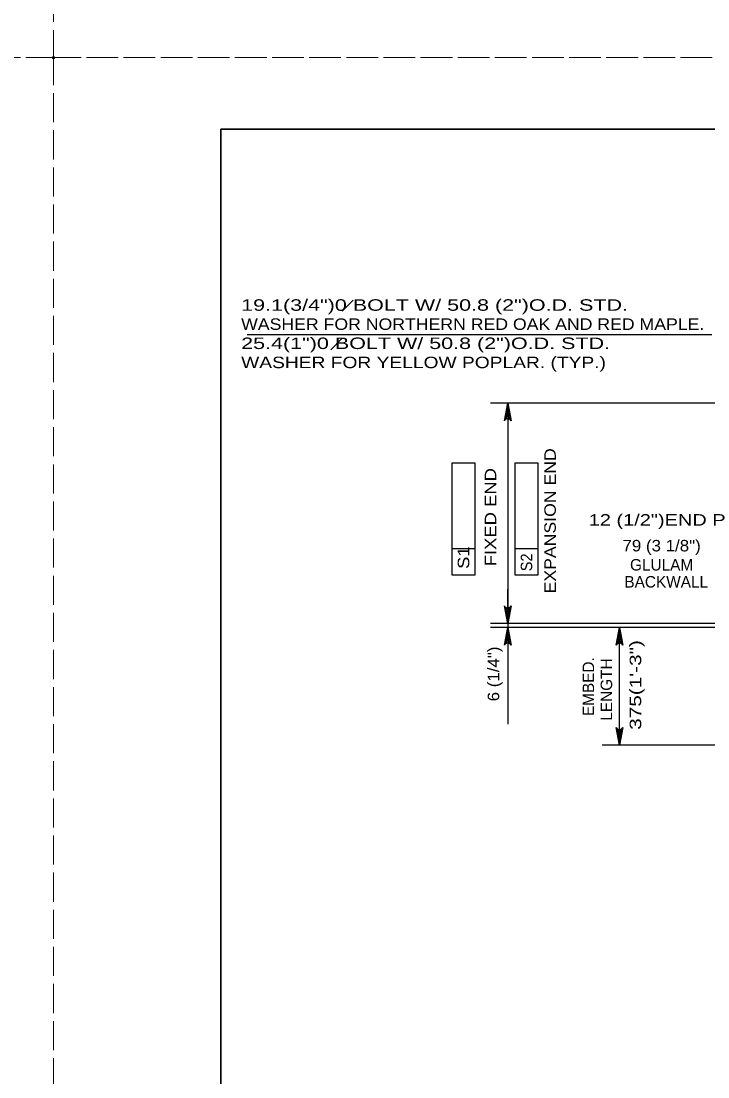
# Model space of a CAD drawing. Extents: x -11 to 79, y -154 to 0.
# Drawn here: x 33.66 to 40.84, y -32.65 to -21.62 of the extents above; entities that cross this region are included whole.
import ezdxf
from ezdxf.enums import TextEntityAlignment as Align

# ---------------------------------------------------------------- set-up
doc = ezdxf.new("R2010")
doc.units = 0
doc.header["$LTSCALE"] = 0.048
doc.header["$PDMODE"] = 32
doc.header["$PDSIZE"] = 0.024
doc.linetypes.add('LONG_DASHED', pattern=[7.5, 6, -1.5])
for name, color, linetype, lineweight in [('1', 7, 'Continuous', 25), ('3', 7, 'Continuous', 25), ('63', 7, 'LONG_DASHED', 13)]:
    doc.layers.add(name, color=color, linetype=linetype, lineweight=lineweight)
doc.layers.add('62', color=7, linetype='Continuous')

msp = doc.modelspace()

# ---------------------------------------------------------------- hatches: boundary and pattern name
at = {"layer": '3'}
for points in [[(38.726, -25.73242), (38.766, -25.73242), (38.746, -25.61242)], [(38.726, -27.79692), (38.766, -27.79692), (38.746, -27.91692)], [(38.726, -28.0765), (38.766, -28.0765), (38.746, -27.9565)], [(39.89308, -28.0765), (39.93308, -28.0765), (39.91308, -27.9565)], [(39.89308, -29.06908), (39.93308, -29.06908), (39.91308, -29.18908)]]:
    msp.add_hatch(color=256, dxfattribs=at).paths.add_polyline_path(points)

# ---------------------------------------------------------------- linework, layer by layer
at = {"layer": '1', "lineweight": 35}
msp.add_lwpolyline([(35.75, -43.25), (67.25, -43.25), (67.25, -22.75), (35.75, -22.75)], close=True, dxfattribs=at)
at = {"layer": '3', "lineweight": 35}
for p, q in [((37.13225, -24.53483), (37.01542, -24.65167)), ((37.01425, -24.93692), (36.89742, -25.05375))]:
    msp.add_line(p, q, dxfattribs=at)
at = {"layer": '3'}
for p, q in [((40.87825, -24.89725), (36.02317, -24.89725)), ((41.44975, -25.61242), (38.566, -25.61242)), ((39.63817, -25.61242), (38.566, -25.61242)), ((38.746, -25.61242), (38.746, -27.7765)), ((38.746, -25.73242), (38.746, -27.79692)), ((38.16517, -26.23492), (38.40142, -26.23492)), ((38.40142, -26.23492), (38.40142, -27.41075)), ((38.82317, -27.41075), (38.82317, -26.23492)), ((38.82317, -26.23492), (39.05942, -26.23492)), ((38.40142, -27.13517), (38.16517, -27.13517)), ((39.05942, -27.13517), (38.82317, -27.13517)), ((38.746, -27.73692), (38.746, -27.55692)), ((38.746, -27.79692), (38.746, -27.67692)), ((41.44975, -27.91692), (38.566, -27.91692)), ((39.63817, -27.91692), (38.566, -27.91692)), ((38.746, -27.91692), (38.746, -27.9565)), ((41.79425, -27.9565), (38.566, -27.9565)), ((38.6835, -27.9565), (38.566, -27.9565)), ((41.44975, -27.9565), (39.73308, -27.9565)), ((39.85058, -27.9565), (39.73308, -27.9565)), ((39.91308, -29.18908), (39.91308, -27.9565)), ((38.746, -28.0765), (38.746, -28.1965)), ((38.746, -28.1365), (38.746, -28.96875)), ((39.91308, -29.06908), (39.91308, -28.0765)), ((42.62758, -29.18908), (39.73308, -29.18908)), ((39.85058, -29.18908), (39.73308, -29.18908))]:
    msp.add_line(p, q, dxfattribs=at)
for points in [[(38.746, -25.61242), (38.78092, -25.79883), (38.771, -25.7845), (38.7585, -25.77708), (38.746, -25.77492), (38.7335, -25.77708), (38.721, -25.7845), (38.71108, -25.79883), (38.746, -25.61242), (38.721, -25.7845), (38.7335, -25.77708), (38.746, -25.61242), (38.746, -25.77492), (38.7585, -25.77708), (38.746, -25.61242), (38.771, -25.7845)], [(38.40142, -27.41075), (38.16517, -27.41075), (38.16517, -26.23492)], [(39.05942, -26.23492), (39.05942, -27.41075), (38.82317, -27.41075)], [(38.746, -27.91692), (38.71108, -27.7305), (38.721, -27.74483), (38.7335, -27.75225), (38.746, -27.75442), (38.7585, -27.75225), (38.771, -27.74483), (38.78092, -27.7305), (38.746, -27.91692), (38.771, -27.74483), (38.7585, -27.75225), (38.746, -27.91692), (38.746, -27.75442), (38.7335, -27.75225), (38.746, -27.91692), (38.721, -27.74483)], [(38.746, -27.9565), (38.78092, -28.14292), (38.771, -28.12858), (38.7585, -28.12117), (38.746, -28.119), (38.7335, -28.12117), (38.721, -28.12858), (38.71108, -28.14292), (38.746, -27.9565), (38.721, -28.12858), (38.7335, -28.12117), (38.746, -27.9565), (38.746, -28.119), (38.7585, -28.12117), (38.746, -27.9565), (38.771, -28.12858)], [(39.91308, -27.9565), (39.948, -28.14292), (39.93808, -28.12858), (39.92558, -28.12117), (39.91308, -28.119), (39.90058, -28.12117), (39.88808, -28.12858), (39.87817, -28.14292), (39.91308, -27.9565), (39.88808, -28.12858), (39.90058, -28.12117), (39.91308, -27.9565), (39.91308, -28.119), (39.92558, -28.12117), (39.91308, -27.9565), (39.93808, -28.12858)], [(39.91308, -29.18908), (39.87817, -29.00267), (39.88808, -29.017), (39.90058, -29.02442), (39.91308, -29.02658), (39.92558, -29.02442), (39.93808, -29.017), (39.948, -29.00267), (39.91308, -29.18908), (39.93808, -29.017), (39.92558, -29.02442), (39.91308, -29.18908), (39.91308, -29.02658), (39.90058, -29.02442), (39.91308, -29.18908), (39.88808, -29.017)]]:
    msp.add_lwpolyline(points, dxfattribs=at)
for points in [[(38.726, -25.73242), (38.766, -25.73242), (38.746, -25.61242)], [(38.726, -27.79692), (38.766, -27.79692), (38.746, -27.91692)], [(38.726, -28.0765), (38.766, -28.0765), (38.746, -27.9565)], [(39.89308, -28.0765), (39.93308, -28.0765), (39.91308, -27.9565)], [(39.89308, -29.06908), (39.93308, -29.06908), (39.91308, -29.18908)]]:
    msp.add_lwpolyline(points, close=True, dxfattribs=at)
at = {"layer": '62'}
msp.add_point((34, -22), dxfattribs=at)
at = {"layer": '63'}
for points in [[(0, -22), (34, -22), (34, 0), (0, 0)], [(34, -22), (68, -22), (68, 0), (34, 0)], [(0, -44), (34, -44), (34, -22), (0, -22)], [(34, -44), (68, -44), (68, -22), (34, -22)]]:
    msp.add_lwpolyline(points, close=True, dxfattribs=at)

# ---------------------------------------------------------------- texts
at = {"layer": '3'}
for s, width, p in [('19.1(3/4")0 BOLT W/ 50.8 (2")O.D. STD. ', 1.4, (35.96092, -24.64667)), ('WASHER FOR NORTHERN RED OAK AND RED MAPLE.', 1.15, (35.96092, -24.84667)), ('25.4(1")0 BOLT W/ 50.8 (2")O.D. STD.', 1.4, (35.96092, -25.04667)), ('WASHER FOR YELLOW POPLAR. (TYP.) ', 1.25, (35.96092, -25.24667))]:
    msp.add_text(s, height=0.12, dxfattribs=dict(at, width=width)).set_placement(p)
for s, width, p in [('EXPANSION END', 1.15, (39.24883, -26.84258)), ('FIXED END', 1.2, (38.626, -26.80446)), ('S1', 1.2, (38.34417, -27.22737)), ('S2', 0.95, (39.00217, -27.27662)), ('375(1\'-3")', 1.35, (40.14067, -28.55829)), ('6 (1/4")', 1.1, (38.65692, -28.44304))]:
    msp.add_text(s, height=0.12, rotation=90, dxfattribs=dict(at, width=width)).set_placement(p, align=Align.CENTER)
at = {"layer": '3', "width": 1.3}
msp.add_text('12 (1/2")END P', height=0.12, dxfattribs=at).set_placement((41.02283, -26.89267), align=Align.RIGHT)
at = {"layer": '3', "width": 1.1}
msp.add_text('79 (3 1/8")', height=0.12, dxfattribs=at).set_placement((40.35404, -27.162), align=Align.CENTER)
at = {"layer": '3'}
for s, p in [('GLULAM', (40.35404, -27.362)), ('BACKWALL', (40.40229, -27.53958))]:
    msp.add_text(s, height=0.12, dxfattribs=at).set_placement(p, align=Align.CENTER)
for s, p in [('EMBED.', (39.64858, -28.57567)), ('LENGTH', (39.83708, -28.606))]:
    msp.add_text(s, height=0.12, rotation=90, dxfattribs=at).set_placement(p, align=Align.CENTER)

doc.saveas('drawing.dxf')
